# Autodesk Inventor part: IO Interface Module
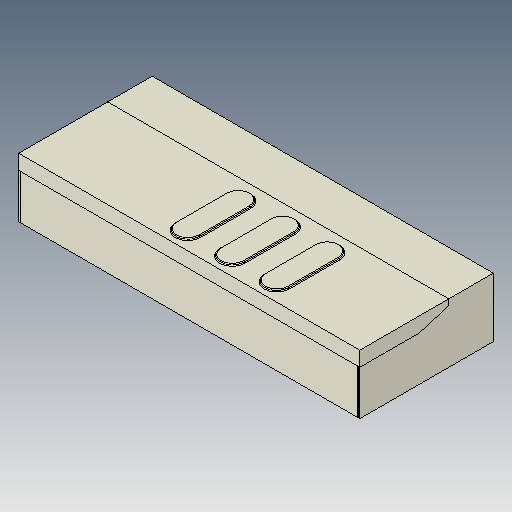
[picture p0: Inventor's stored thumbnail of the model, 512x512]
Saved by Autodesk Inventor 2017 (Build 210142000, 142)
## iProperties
Created: 2005-12
Part Number: IO Interface Module
Material: Generic
Document SubType Name: Modeling
Designer: DanielSeverino
Density: 1 g/cm^3
Appearance: Default
Author: DanielSeverino
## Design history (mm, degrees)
feature "Solid1"
body "Solid2"
